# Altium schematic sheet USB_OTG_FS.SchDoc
size A4; DocumentNumber: 5; Revision: B.2(PCB.SCH); SheetNumber: 5; SheetTotal: 6
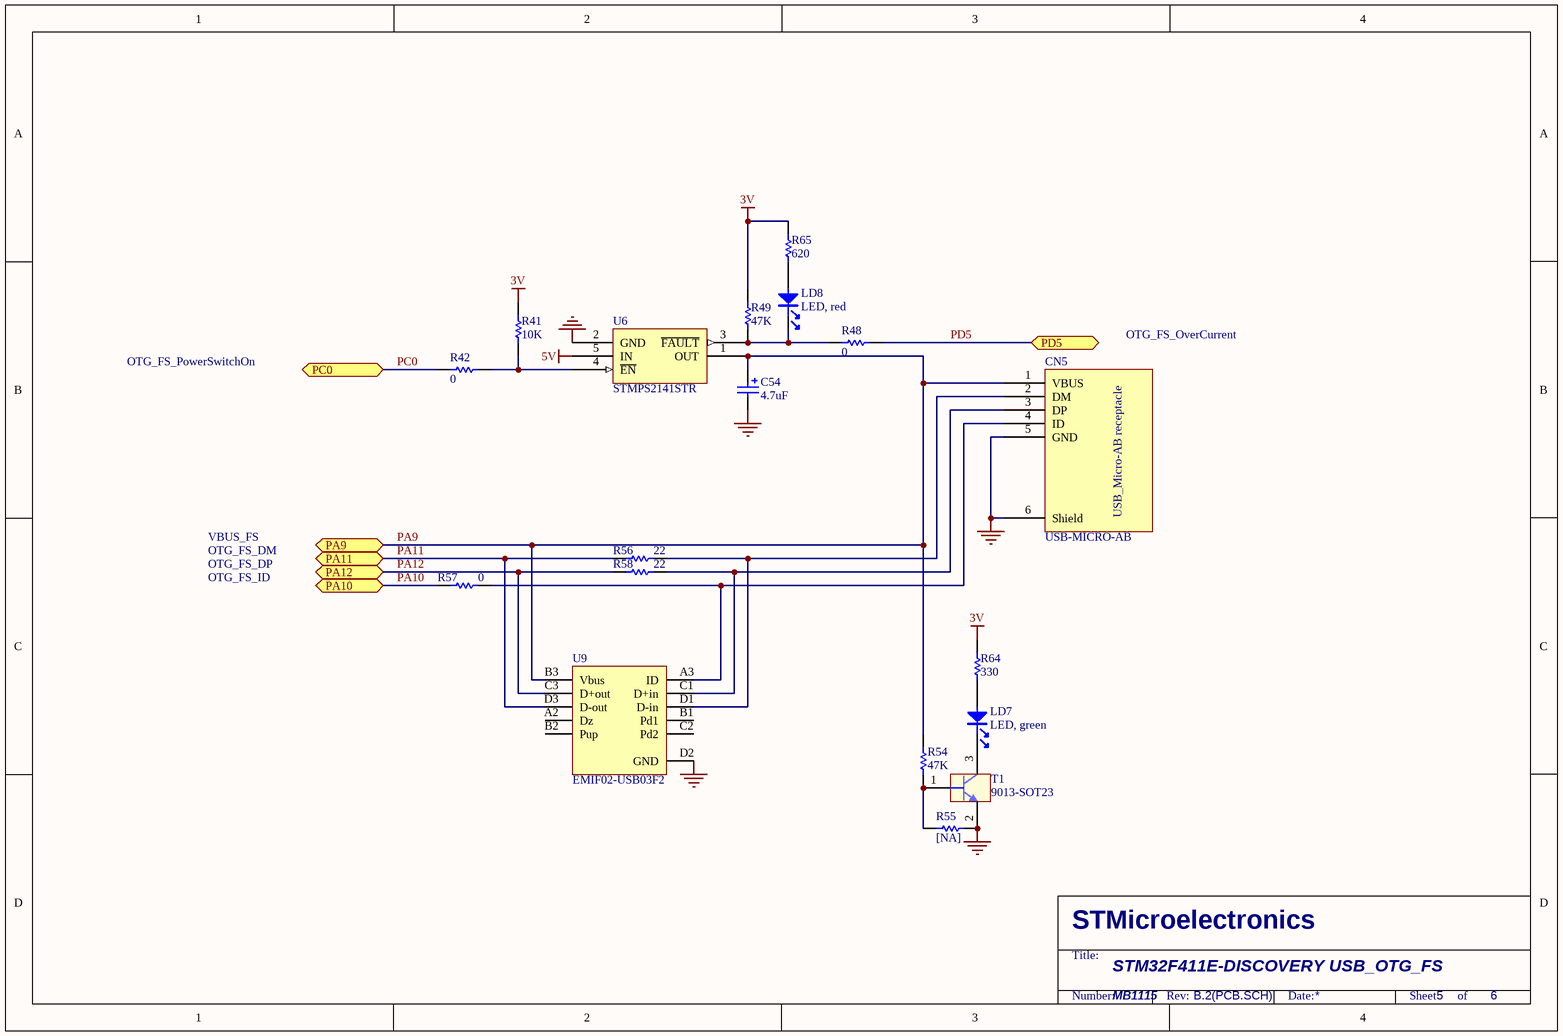
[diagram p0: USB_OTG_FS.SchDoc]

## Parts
C54  4.7uF  [TAN-A]
CN5  USB-MICRO-AB  [USB-MICRO-AB]
LD7  LED, green  [0603D]
LD8  LED, red  [0603D]
R41  10K  [0402R]
R42  0  [0402R]
R48  0  [0402R]
R49  47K  [0402R]
R54  47K  [0402R]
R55  [NA]  [0402R]
R56  22  [0402R]
R57  0  [0402R]
R58  22  [0402R]
R64  330  [0603R]
R65  620  [0603R]
T1  9013-SOT23  [SOT-23]
U6  STMPS2141STR  [SOT23-5L]
U9  EMIF02-USB03F2  [Flip Chip]

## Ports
PA9, PA10, PA11, PA12, PC0, PD5

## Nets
3V: R41.1 R49.1 R64.2 R65.2
5V: U6.5(IN)
GND: C54.2 CN5.5(GND) CN5.6(Shield) R55.2 T1.2(E) U6.2(GND) U9.D2(GND)
PA9: C54.1 CN5.1(VBUS) R54.2 U6.1(OUT) U9.B3(Vbus) ; port PA9
PA10: R57.1 ; port PA10
PA11: R56.2 U9.D3(D-out) ; port PA11
PA12: R58.2 U9.C3(D+out) ; port PA12
PC0: R42.1 ; port PC0
PD5: R48.2 ; port PD5
NetCN5_2: CN5.2(DM) R56.1 U9.D1(D-in)
NetCN5_3: CN5.3(DP) R58.1 U9.C1(D+in)
NetCN5_4: CN5.4(ID) R57.2 U9.A3(ID)
NetLD7_1: LD7.1 R64.1
NetLD7_2: LD7.2 T1.3(C)
NetLD8_1: LD8.1 R65.1
NetLD8_2: LD8.2 R48.1 R49.2 U6.3(~{FAULT})
NetR41_2: R41.2 R42.2 U6.4(~{EN})
NetR54_1: R54.1 R55.1 T1.1(B)

Not connected (* = marked no-connect by the designer): U9 A2(Dz) B1(Pd1) B2(Pup) C2(Pd2)

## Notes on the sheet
- OTG_FS_PowerSwitchOn
- OTG_FS_OverCurrent
- VBUS_FS
- OTG_FS_ID
- OTG_FS_DM
- OTG_FS_DP
- STM32F411E-DISCOVERY USB_OTG_FS
- MB1115

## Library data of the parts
C54 = Cap_4.7uF_POL_10%_TANA: Polarized Capacitor,4.7uF,16V,10%,typeA,AVX; Manuf_Part_1: TAJA475K016R
CN5 = USB-MICRO-AB: USB-MICRO-AB, 47590-0001, SMT, MOLEX; Ref St: xxxxxxx
LD7 = LED_green: LED, green, 0603; Manuf_1: everlight; Manuf_Part_1: 19-213SYGC/S530-E2/TR8; Description: LED,green,0603,19-213SYGC/S530-E2/TR8,everlight
LD8 = LED_red: LED, red, 0603; Manuf_1: everlight; Manuf_Part_1: 19-213-R6C-AP1Q2B/3T; Description: LED,red,0603,19-213-R6C-AP1Q2B/3T,everlight
R41 R49 R54 R64 = res1: Resistor; Value: 1K
R42 R48 R57 = Res_0_0402: Resistor,0,0402
R55 = Res_NA_0402: Resistor,[NA],0402; Fitted: NO
R56 R58 R65 = Res1: Resistor; Value: 1K
T1 = 9013-SOT23: NPN Bipolar Transistor; Manuf_1: unisonic; Manuf_Part_1: MMBT9013; Description: NPN Bipolar Transistor, SOT-23 Footprint
U6 = STMPS2141STR: Enhanced single channel power switches; Manuf_1: STM; Provided: ST; ECCN_US/EU: EAR99/NEC; Ref St: 9159003
U9 = EMIF02-USB03F2: 2-line IPAD, EMI filter including ESD protection; Manuf_1: STM; Provided: ST; ECCN_US/EU: EAR99/NEC; Ref St: 9179037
